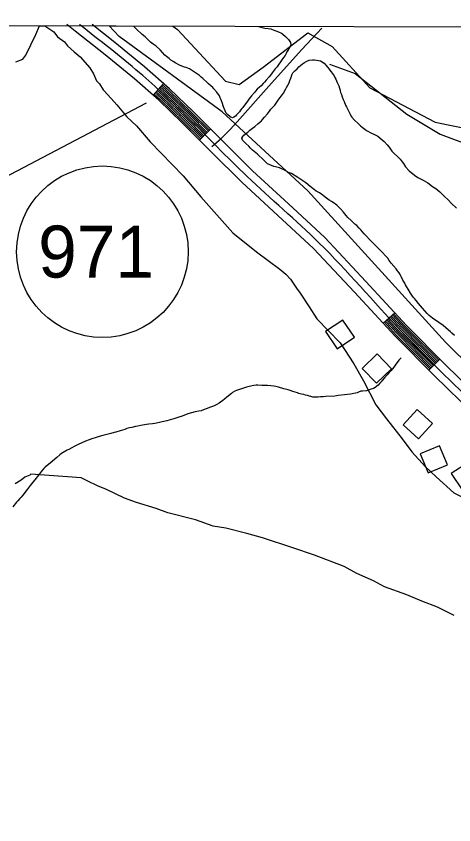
# Model space of a CAD drawing. Extents: x 3161564 to 3199464, y 849354 to 874788.
# Drawn here: x 3172453 to 3173295, y 871452 to 873008 of the extents above; entities that cross this region are included whole.
import ezdxf

# ---------------------------------------------------------------- set-up
doc = ezdxf.new("R2010")
doc.units = 0
for name, color, linetype in [('V-BLDG-OTLN', 7, 'Continuous'), ('V-GRID-FRAM', 7, 'Continuous'), ('V-ROAD-CNTR', 7, 'Continuous'), ('V-ROAD-IDEN', 7, 'Continuous'), ('V-SITE-VEGE', 7, 'Continuous'), ('V-TOPO-SHOR', 7, 'Continuous')]:
    doc.layers.add(name, color=color, linetype=linetype)

msp = doc.modelspace()

# ---------------------------------------------------------------- linework, layer by layer
at = {"layer": 'V-BLDG-OTLN'}
for points in [[(3173070.5478220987, 872367.4022375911), (3173103.7117557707, 872389.7641928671), (3173081.349800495, 872422.929126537), (3173048.1848668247, 872400.5671712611)], [(3173118.606725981, 872329.9433125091), (3173146.3426705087, 872301.1213701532), (3173175.1646128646, 872328.8563146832), (3173147.429668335, 872357.6792570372)], [(3173197.803567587, 872221.1485300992), (3173227.3615084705, 872194.1985839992), (3173254.311454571, 872223.7575248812), (3173224.7525136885, 872250.7074709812)], [(3173230.557502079, 872165.5876412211), (3173245.9314713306, 872128.6597150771), (3173282.858397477, 872144.0326843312), (3173267.485428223, 872180.960610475)], [(3173312.1623388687, 872094.2477839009), (3173345.6122719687, 872116.179740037), (3173323.6803158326, 872149.630673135), (3173290.2293827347, 872127.698716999)]]:
    msp.add_lwpolyline(points, close=True, dxfattribs=at)
at = {"layer": 'V-GRID-FRAM'}
msp.add_lwpolyline([(3165819.245, 873007.562), (3197186.656, 872920.878), (3197144.3310000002, 854733.305), (3165761.0470000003, 854820.033), (3165819.245, 873007.562)], dxfattribs=at)
at = {"layer": 'V-ROAD-CNTR'}
for p, q in [((3172716.635529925, 872855.3902616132), (3172736.5654900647, 872877.8142167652)), ((3172805.893351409, 872769.1114341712), (3172827.048309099, 872790.382391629)), ((3173159.3266445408, 872416.7121389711), (3173181.356600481, 872437.0750982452)), ((3173246.814469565, 872326.729318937), (3173268.128426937, 872347.8412767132))]:
    msp.add_line(p, q, dxfattribs=at)
for points in [[(3173333.7932956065, 872241.4854894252), (3173257.529448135, 872315.9123405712), (3173182.236598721, 872391.9271885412), (3173103.857755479, 872476.7210189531), (3173025.443912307, 872560.385851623), (3172956.7340497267, 872624.287723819), (3172887.0671890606, 872688.3535956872), (3172829.598303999, 872745.535481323), (3172772.3904184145, 872802.4323675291), (3172727.3935084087, 872845.8282807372), (3172680.860601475, 872887.1861980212), (3172624.0087151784, 872933.2991057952), (3172566.4518302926, 872979.0080143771), (3172550.6258619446, 872991.502989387)], [(3174323.151316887, 871475.958020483), (3174224.1495148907, 871536.5578992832), (3174124.9837132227, 871597.9347765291), (3174014.442934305, 871660.5176513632), (3173904.622153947, 871722.9685264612), (3173864.9882332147, 871749.3314737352), (3173826.8323095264, 871778.295415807), (3173779.5474040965, 871817.6653370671), (3173734.953493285, 871859.8592526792), (3173684.7135937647, 871914.028144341), (3173637.246688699, 871972.009028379), (3173355.035253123, 872262.6734470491), (3173278.665405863, 872337.204297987), (3173203.9145553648, 872412.671147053), (3173125.8177115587, 872497.1609780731), (3173046.627869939, 872581.6518090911), (3172977.1040089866, 872646.3136797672), (3172907.809147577, 872710.0355523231), (3172850.754261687, 872766.8054387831), (3172793.3823764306, 872823.8663246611), (3172747.7794676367, 872867.846236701), (3172700.284562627, 872910.0601522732), (3172642.7866776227, 872956.6950590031), (3172599.126764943, 872991.368989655)], [(3172829.265000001, 872756.6959999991), (3172847.240000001, 872772.199999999), (3172864.634000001, 872789.324999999), (3172878.362000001, 872804.2799999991), (3172939.457000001, 872873.1009999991), (3173001.780000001, 872943.1159999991), (3173021.648000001, 872964.0439999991), (3173041.309000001, 872984.773999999)], [(3172814.354334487, 872777.6204171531), (3172780.7874016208, 872811.0063503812), (3172735.547492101, 872854.6352631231), (3172724.6065139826, 872864.3602436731)], [(3172816.4703302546, 872779.747412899), (3172782.8863974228, 872813.1493460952), (3172737.586488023, 872856.837258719), (3172726.599509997, 872866.6022391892)], [(3172818.5863260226, 872781.8744086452), (3172784.9853932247, 872815.292341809), (3172739.625483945, 872859.0392543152), (3172728.592506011, 872868.844234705)], [(3172820.701321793, 872784.001404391), (3172787.0843890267, 872817.4363375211), (3172741.663479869, 872861.2412499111), (3172730.5855020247, 872871.0872302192)], [(3172822.817317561, 872786.1284001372), (3172789.1843848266, 872819.579333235), (3172743.702475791, 872863.4422455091), (3172732.578498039, 872873.3292257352)], [(3172824.932313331, 872788.2553958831), (3172791.2833806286, 872821.722328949), (3172745.740471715, 872865.6442411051), (3172734.571494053, 872875.571221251)], [(3172808.0083471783, 872771.2394299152), (3172774.489414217, 872804.5763632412), (3172729.4325043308, 872848.0302763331), (3172718.627525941, 872857.633257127)], [(3172810.123342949, 872773.3664256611), (3172776.588410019, 872806.7193589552), (3172731.4705002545, 872850.232271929), (3172720.6205219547, 872859.8752526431)], [(3172812.2393387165, 872775.493421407), (3172778.6884058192, 872808.8623546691), (3172733.5094961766, 872852.4332675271), (3172722.613517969, 872862.1172481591)], [(3173257.471448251, 872337.2862978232), (3173193.0755770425, 872402.2991677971), (3173170.341622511, 872426.894118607)], [(3173259.602443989, 872339.3972936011), (3173195.243572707, 872404.3731636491), (3173172.544618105, 872428.9301145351)], [(3173261.734439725, 872341.5082893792), (3173197.411568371, 872406.4481594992), (3173174.747613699, 872430.967110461)], [(3173263.865435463, 872343.620285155), (3173199.5795640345, 872408.5221553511), (3173176.950609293, 872433.0031063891)], [(3173265.9974311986, 872345.7312809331), (3173201.746559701, 872410.597151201), (3173179.153604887, 872435.0391023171)], [(3173248.9454653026, 872328.841314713), (3173184.4045943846, 872394.0011843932), (3173161.529640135, 872418.749134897)], [(3173251.0774610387, 872330.9523104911), (3173186.5715900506, 872396.076180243), (3173163.732635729, 872420.785130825)], [(3173253.2084567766, 872333.0643062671), (3173188.739585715, 872398.1501760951), (3173165.935631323, 872422.8211267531)], [(3173255.3404525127, 872335.1753020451), (3173190.907581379, 872400.225171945), (3173168.138626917, 872424.858122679)]]:
    msp.add_lwpolyline(points, dxfattribs=at)
msp.add_spline([(3173344.4142743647, 872252.0794682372), (3173193.0755770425, 872402.2991677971), (3173036.035891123, 872571.0188303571), (3172897.438168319, 872699.1945740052), (3172782.8863974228, 872813.1493460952), (3172690.5725820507, 872898.6231751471), (3172575.763811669, 872990.7679908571), (3172574.9178133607, 872991.4359895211)], degree=3, dxfattribs=at)
at = {"layer": 'V-ROAD-IDEN'}
msp.add_circle((3172618.975347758, 872554.3852328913), 165.0000000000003, dxfattribs=at)
msp.add_circle((3172618.975347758, 872554.3852328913), 165.0000000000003, dxfattribs=at)
at = {"layer": 'V-SITE-VEGE'}
for p, q in [((3172490.943000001, 872972.3429999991), (3172498.1904244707, 872989.1047003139)), ((3172498.1904244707, 872989.1047003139), (3172508.5101719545, 872989.0761816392)), ((3172508.5101719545, 872989.0761816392), (3172525.247000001, 872977.591999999)), ((3172650.974, 872968.7589999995), (3172631.7205323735, 872988.7356891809)), ((3172631.7205323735, 872988.7356891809), (3172754.785737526, 872988.3955978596)), ((3172754.785737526, 872988.3955978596), (3172763.329, 872981.9849999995)), ((3172471.393000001, 872932.662999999), (3172490.943000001, 872972.3429999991)), ((3172525.247000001, 872977.591999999), (3172532.729000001, 872967.981999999)), ((3172763.329, 872981.9849999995), (3172855.856, 872882.7979999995)), ((3172928.558, 872909.2479999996), (3173014.4760000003, 872975.3719999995)), ((3173014.4760000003, 872975.3719999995), (3173060.738, 872948.9219999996)), ((3172532.729000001, 872967.981999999), (3172545.912000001, 872958.2949999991)), ((3172545.912000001, 872958.2949999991), (3172551.515000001, 872950.6129999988)), ((3172849.247, 872823.2849999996), (3172650.974, 872968.7589999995)), ((3172551.515000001, 872950.6129999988), (3172564.676000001, 872939.0259999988)), ((3173060.738, 872948.9219999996), (3173133.44, 872869.5719999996)), ((3172452.197000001, 872919.606999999), (3172465.587000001, 872925.133999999)), ((3172465.587000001, 872925.133999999), (3172471.393000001, 872932.662999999)), ((3172564.676000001, 872939.0259999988), (3172575.958000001, 872929.3649999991)), ((3172575.958000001, 872929.3649999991), (3172594.693000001, 872908.192999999)), ((3172882.294, 872876.1849999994), (3172928.5580000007, 872909.2479999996)), ((3172594.693000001, 872908.192999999), (3172602.150000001, 872896.680999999)), ((3172602.150000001, 872896.680999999), (3172607.675000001, 872883.295999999)), ((3172607.675000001, 872883.295999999), (3172613.303000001, 872877.511999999)), ((3172855.8560000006, 872882.7979999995), (3172882.294, 872876.1849999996)), ((3172613.3030000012, 872877.511999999), (3172620.760000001, 872866.001999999)), ((3172620.760000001, 872866.001999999), (3172622.636000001, 872864.074999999)), ((3172622.636000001, 872864.074999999), (3172641.371000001, 872842.9029999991)), ((3173133.44, 872869.5719999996), (3173259.0130000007, 872803.4479999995)), ((3172641.371000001, 872842.9029999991), (3172647.001000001, 872837.1209999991)), ((3172647.001000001, 872837.1209999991), (3172665.7120000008, 872814.0489999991)), ((3173014.4760000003, 872671.1989999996), (3172849.247, 872823.2849999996)), ((3172665.7120000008, 872814.0489999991), (3172684.5000000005, 872796.6789999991)), ((3173259.0130000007, 872803.4479999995), (3173358.1460000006, 872783.6109999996)), ((3172684.500000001, 872796.6789999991), (3172710.716000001, 872765.8979999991)), ((3172710.716000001, 872765.8979999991), (3172774.5100000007, 872700.3779999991)), ((3172774.510000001, 872700.3779999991), (3172808.205000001, 872659.9879999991)), ((3173278.84, 872380.2489999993), (3173014.4760000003, 872671.1989999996)), ((3172808.205000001, 872659.9879999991), (3172870.047000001, 872590.6919999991)), ((3172870.047000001, 872590.6919999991), (3172915.201000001, 872553.9509999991)), ((3172915.201000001, 872553.9509999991), (3172960.4090000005, 872521.0129999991)), ((3172960.409000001, 872521.0129999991), (3172971.691000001, 872511.351999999)), ((3172971.691000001, 872511.3519999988), (3172981.073000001, 872501.7179999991)), ((3172981.073000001, 872501.7179999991), (3172992.255000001, 872484.4519999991)), ((3172992.255000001, 872484.4519999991), (3172999.732000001, 872474.839999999)), ((3172999.7320000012, 872474.839999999), (3173016.495000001, 872447.988999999)), ((3173016.495000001, 872447.988999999), (3173031.400000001, 872424.966999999)), ((3173031.400000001, 872424.966999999), (3173076.432000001, 872378.716999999)), ((3173635.732, 872029.7939999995), (3173278.84, 872380.2489999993)), ((3173076.432000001, 872378.716999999), (3173102.5190000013, 872338.4289999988)), ((3173102.5190000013, 872338.4289999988), (3173121.103000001, 872305.8479999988)), ((3173121.103000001, 872305.8479999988), (3173145.2180000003, 872259.8779999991)), ((3173145.218000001, 872259.8779999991), (3173165.780000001, 872232.9759999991)), ((3173165.780000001, 872232.9759999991), (3173195.697000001, 872194.5369999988)), ((3173195.697000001, 872194.5369999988), (3173214.385000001, 872169.5609999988)), ((3173214.385000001, 872169.5609999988), (3173240.624000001, 872140.6799999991)), ((3173240.6240000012, 872140.6799999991), (3173261.292000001, 872121.3859999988)), ((3172470.058000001, 872120.537999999), (3172462.3760000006, 872114.934999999)), ((3172479.618000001, 872124.216999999), (3172470.058000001, 872120.5379999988)), ((3172481.541000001, 872126.0929999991), (3172479.6180000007, 872124.216999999)), ((3172578.450000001, 872119.0929999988), (3172481.541000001, 872126.0929999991)), ((3172589.784000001, 872113.234999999), (3172578.450000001, 872119.0929999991)), ((3173261.2920000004, 872121.3859999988), (3173295.1130000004, 872090.501999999)), ((3172462.376000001, 872114.9349999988), (3172450.864000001, 872107.4799999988)), ((3172610.577000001, 872103.4479999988), (3172589.7840000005, 872113.2349999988)), ((3172625.712000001, 872097.5389999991), (3172610.577000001, 872103.447999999)), ((3172661.616000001, 872079.942999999), (3172625.712000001, 872097.5389999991)), ((3173295.113000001, 872090.501999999), (3173310.223000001, 872082.692999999)), ((3172684.334000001, 872072.0319999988), (3172661.616000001, 872079.942999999)), ((3172722.214000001, 872060.111999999), (3172684.334000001, 872072.0319999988)), ((3172744.932000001, 872052.202999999), (3172722.214000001, 872060.1119999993)), ((3172798.000000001, 872038.177999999), (3172744.932000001, 872052.2029999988)), ((3172832.077000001, 872026.3139999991), (3172798.000000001, 872038.177999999)), ((3172856.747000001, 872022.1789999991), (3172832.077000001, 872026.3139999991)), ((3172896.554000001, 872012.1379999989), (3172856.747000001, 872022.1789999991)), ((3172926.879000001, 872004.1259999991), (3172896.554000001, 872012.1379999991)), ((3172985.576000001, 871984.3219999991), (3172926.879000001, 872004.1259999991)), ((3173027.235000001, 871970.452999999), (3172985.576000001, 871984.3219999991)), ((3173084.003000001, 871948.7729999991), (3173027.235000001, 871970.452999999)), ((3173108.546000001, 871935.1309999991), (3173084.003000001, 871948.7729999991)), ((3173140.6980000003, 871921.386999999), (3173108.546000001, 871935.1309999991)), ((3173161.463000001, 871909.6989999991), (3173140.6980000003, 871921.386999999)), ((3173204.997000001, 871893.900999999), (3173161.463000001, 871909.6989999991)), ((3173233.368000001, 871882.1099999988), (3173204.9970000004, 871893.9009999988)), ((3173263.6440000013, 871870.292999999), (3173233.368000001, 871882.1099999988)), ((3173295.766000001, 871854.648999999), (3173263.6440000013, 871870.292999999))]:
    msp.add_line(p, q, dxfattribs=at)
at = {"layer": 'V-TOPO-SHOR'}
for points in [[(3172980.538000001, 872949.363999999), (3172977.853000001, 872944.9589999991), (3172976.203000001, 872942.3559999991), (3172974.140000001, 872939.1549999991), (3172972.479000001, 872935.7449999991), (3172970.814000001, 872932.133999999), (3172967.726000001, 872927.7329999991), (3172962.799000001, 872921.5419999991), (3172957.441000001, 872913.5399999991), (3172954.969000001, 872909.939999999), (3172951.483000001, 872905.947999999), (3172947.781000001, 872900.9509999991), (3172945.726000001, 872898.356999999), (3172942.439000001, 872894.1599999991), (3172939.767000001, 872890.5639999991), (3172934.032000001, 872884.5839999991), (3172930.751000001, 872880.792999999), (3172928.495000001, 872878.197999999), (3172924.194000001, 872873.6149999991), (3172920.925000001, 872870.8309999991), (3172916.633000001, 872866.851999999), (3172913.352000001, 872863.060999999), (3172911.300000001, 872860.6669999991), (3172905.760000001, 872854.0809999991), (3172902.884000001, 872850.484999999), (3172899.186000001, 872845.689999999), (3172896.716000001, 872842.2899999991), (3172892.597000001, 872836.2919999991), (3172889.310000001, 872832.0959999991), (3172887.260000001, 872829.9019999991), (3172884.995000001, 872826.501999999), (3172882.531000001, 872823.5059999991), (3172880.479000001, 872821.111999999), (3172877.204000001, 872817.724999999), (3172874.7490000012, 872815.334999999), (3172872.097000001, 872813.351999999), (3172869.250000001, 872811.7749999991), (3172864.834000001, 872813.6529999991), (3172859.647000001, 872818.1649999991), (3172857.265000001, 872821.224999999), (3172855.104000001, 872825.6959999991), (3172851.971000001, 872832.8039999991), (3172849.266000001, 872841.7229999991), (3172847.127000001, 872847.809999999), (3172845.753000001, 872850.6549999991), (3172843.986000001, 872854.3119999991), (3172839.435000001, 872861.238999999), (3172833.471000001, 872867.9809999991), (3172831.280000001, 872870.2309999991), (3172827.694000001, 872873.712999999), (3172823.299000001, 872877.204999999), (3172820.508000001, 872879.6639999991), (3172812.338000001, 872887.6499999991), (3172809.147000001, 872890.518999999), (3172805.549000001, 872893.1909999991), (3172799.956000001, 872897.506999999), (3172796.351000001, 872899.7779999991), (3172786.349000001, 872906.371999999), (3172783.338000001, 872907.8259999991), (3172780.123000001, 872908.878999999), (3172776.902000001, 872909.5279999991), (3172768.867000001, 872912.464999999), (3172759.250000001, 872917.8429999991), (3172756.243000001, 872919.4999999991), (3172750.837000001, 872922.802999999), (3172747.244000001, 872925.881999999), (3172742.251000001, 872929.7829999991), (3172739.263000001, 872932.8529999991), (3172730.316000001, 872942.8679999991), (3172722.130000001, 872949.6399999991), (3172716.731000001, 872953.547999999), (3172711.540000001, 872957.655999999), (3172706.751000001, 872961.9609999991), (3172701.181000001, 872967.8919999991), (3172695.793000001, 872972.608999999), (3172684.819000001, 872982.246999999), (3172679.010831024, 872988.6050021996)], [(3172919.131326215, 872987.9414279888), (3172919.885000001, 872987.5349999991), (3172923.706000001, 872986.4739999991), (3172931.356000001, 872984.7549999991), (3172938.001000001, 872983.655999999), (3172943.039000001, 872982.981999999), (3172948.866000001, 872980.8849999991), (3172952.884000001, 872979.415999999), (3172957.900000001, 872977.126999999), (3172963.319000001, 872974.832999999), (3172966.323000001, 872972.974999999), (3172971.1070000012, 872968.469999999), (3172974.495000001, 872965.192999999), (3172976.883000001, 872962.736999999), (3172981.040000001, 872956.623999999), (3172981.386000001, 872952.3809999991), (3172980.538000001, 872949.363999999)], [(3172891.137000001, 872778.6689999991), (3172898.485000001, 872784.626999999), (3172902.573000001, 872788.204999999), (3172908.072000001, 872791.763999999), (3172912.154000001, 872795.138999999), (3172918.283000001, 872800.506999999), (3172921.757000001, 872803.488999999), (3172924.825000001, 872806.474999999), (3172927.075000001, 872808.665999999), (3172931.175000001, 872813.253999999), (3172936.713000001, 872819.6399999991), (3172940.617000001, 872824.6329999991), (3172943.291000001, 872828.4319999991), (3172947.600000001, 872833.420999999), (3172950.470000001, 872836.6109999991), (3172957.054000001, 872845.810999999), (3172959.110000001, 872848.608999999), (3172960.961000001, 872851.006999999), (3172965.682000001, 872856.795999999), (3172967.333000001, 872859.3969999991), (3172971.886000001, 872867.613999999), (3172973.135000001, 872870.4239999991), (3172975.820000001, 872874.8269999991), (3172978.103000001, 872879.4389999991), (3172979.778000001, 872883.858999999), (3172981.251000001, 872888.2799999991), (3172982.719000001, 872892.2989999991), (3172983.774000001, 872895.716999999), (3172985.630000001, 872898.515999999), (3172989.320000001, 872902.7059999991), (3172993.611000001, 872906.4829999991), (3172997.092000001, 872910.0709999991), (3173000.361000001, 872912.851999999), (3173003.834000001, 872916.0369999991), (3173007.705000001, 872918.606999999), (3173012.381000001, 872920.9659999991), (3173016.845000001, 872922.7239999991), (3173023.524000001, 872923.8439999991), (3173027.157000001, 872923.7949999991), (3173031.185000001, 872923.1349999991), (3173038.632000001, 872921.4169999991), (3173045.437000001, 872917.087999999), (3173048.815000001, 872913.003999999), (3173052.591000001, 872908.7109999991), (3173054.574000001, 872906.060999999), (3173058.938000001, 872900.3489999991), (3173064.691000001, 872892.7999999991), (3173066.061000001, 872889.5519999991), (3173068.035000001, 872886.295999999), (3173070.777000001, 872880.2009999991), (3173073.712000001, 872873.2969999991), (3173076.221000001, 872864.785999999), (3173077.376000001, 872860.5299999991), (3173078.939000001, 872856.6719999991), (3173080.094000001, 872852.618999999), (3173082.043000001, 872847.545999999), (3173084.005000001, 872843.2799999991), (3173086.942000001, 872836.5769999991), (3173088.712000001, 872833.121999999), (3173095.388000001, 872819.3039999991)], [(3173055.805234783, 872915.2516869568), (3173105.5434608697, 872897.4880347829), (3173205.0199130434, 872819.3279652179), (3173268.96906087, 872780.2479304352), (3174334.788191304, 872382.3421217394), (3175333.105443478, 872012.858156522)], [(3171898.5032956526, 872394.7766782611), (3171926.9251391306, 872419.6457913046), (3172392.3328260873, 872677.2187478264), (3172704.084921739, 872840.6443478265)], [(3173095.388000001, 872819.3039999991), (3173096.754000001, 872815.8529999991), (3173099.138000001, 872812.993999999), (3173104.111000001, 872807.4739999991), (3173111.0900000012, 872801.121999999), (3173115.475000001, 872796.822999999), (3173118.870000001, 872794.1519999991), (3173123.665000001, 872790.4539999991), (3173127.060000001, 872787.7829999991), (3173136.676000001, 872782.199999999), (3173140.893000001, 872780.528999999), (3173145.103000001, 872778.4519999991), (3173148.716000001, 872776.7889999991), (3173157.297000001, 872769.606999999), (3173160.891000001, 872766.530999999), (3173166.8570000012, 872759.986999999), (3173170.435000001, 872755.6989999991), (3173175.981000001, 872747.952999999), (3173178.369000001, 872745.2949999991), (3173188.941000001, 872735.8659999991), (3173191.921000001, 872732.3949999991), (3173195.892000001, 872727.4959999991), (3173198.265000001, 872723.827999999), (3173202.423000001, 872717.716999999), (3173208.9820000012, 872710.1579999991), (3173219.366000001, 872701.7379999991), (3173226.171000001, 872697.4069999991), (3173232.182000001, 872694.094999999), (3173236.397000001, 872692.2209999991), (3173244.800000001, 872686.6569999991), (3173253.993000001, 872679.8699999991), (3173260.197000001, 872675.746999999), (3173264.192000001, 872672.6649999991), (3173268.186000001, 872669.381999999), (3173276.550000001, 872660.988999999), (3173284.926000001, 872653.4079999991), (3173290.100000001, 872647.682999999), (3173300.059000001, 872637.856999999)], [(3173296.334000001, 872393.0249999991), (3173291.550000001, 872397.5299999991), (3173288.758000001, 872400.192999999), (3173285.166000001, 872403.268999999), (3173274.586000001, 872412.0939999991), (3173266.193000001, 872418.464999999), (3173253.789000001, 872426.709999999), (3173247.796000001, 872431.432999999), (3173243.813000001, 872435.3239999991), (3173234.865000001, 872445.5399999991), (3173227.322000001, 872454.9299999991), (3173222.548000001, 872460.241999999), (3173219.573000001, 872464.118999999), (3173217.193000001, 872467.1789999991), (3173212.044000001, 872474.719999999), (3173207.100000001, 872482.2559999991), (3173204.3400000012, 872487.138999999), (3173202.372000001, 872490.797999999), (3173200.596000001, 872493.851999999), (3173197.243000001, 872499.751999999), (3173193.905000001, 872506.6599999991), (3173191.939000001, 872510.5229999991), (3173190.163000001, 872513.5759999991), (3173186.788000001, 872517.8609999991), (3173184.009000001, 872521.3319999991), (3173174.871000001, 872532.155999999), (3173170.902000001, 872537.2549999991), (3173167.934000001, 872541.7359999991), (3173165.548000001, 872544.3949999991), (3173155.798000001, 872554.822999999), (3173148.433000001, 872562.5929999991), (3173137.681000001, 872573.6419999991), (3173122.747000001, 872588.9859999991), (3173116.186000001, 872596.341999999), (3173113.202000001, 872599.6129999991), (3173108.221000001, 872604.525999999), (3173104.831000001, 872607.599999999), (3173097.854000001, 872614.155999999), (3173091.481000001, 872620.4999999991), (3173087.892000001, 872623.981999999), (3173082.932000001, 872630.305999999), (3173077.966000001, 872636.2289999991), (3173069.997000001, 872644.209999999), (3173063.196000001, 872648.743999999), (3173059.997000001, 872651.006999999), (3173055.389000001, 872653.6939999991), (3173050.189000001, 872657.197999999), (3173044.198000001, 872662.123999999), (3173041.405000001, 872664.5859999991), (3173036.801000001, 872667.4729999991), (3173034.200000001, 872669.123999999), (3173030.389000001, 872670.991999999), (3173026.989000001, 872673.461999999), (3173018.398000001, 872680.037999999), (3173010.214000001, 872686.809999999), (3173002.612000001, 872691.9609999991), (3172995.007000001, 872696.908999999), (3172982.998000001, 872704.5419999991), (3172977.1780000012, 872707.0449999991), (3172974.165000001, 872708.295999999), (3172970.358000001, 872710.366999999), (3172959.530000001, 872715.7629999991), (3172952.2860000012, 872717.677999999), (3172948.862000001, 872718.1279999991), (3172944.244000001, 872720.0079999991), (3172936.822000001, 872723.540999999), (3172932.834000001, 872727.229999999), (3172930.641000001, 872729.2779999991), (3172926.858000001, 872733.1649999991), (3172920.079000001, 872739.515999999), (3172917.288000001, 872741.974999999), (3172914.294000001, 872744.4389999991), (3172910.900000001, 872747.309999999), (3172907.906000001, 872749.976999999), (3172904.123000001, 872753.863999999), (3172900.535000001, 872757.1429999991), (3172894.758000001, 872762.8729999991), (3172891.174000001, 872766.5549999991), (3172888.788000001, 872769.2139999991), (3172887.424000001, 872772.8649999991), (3172888.884000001, 872776.2769999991), (3172891.137000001, 872778.6689999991)], [(3173193.649000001, 872350.0739999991), (3173189.551000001, 872345.6869999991), (3173186.262000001, 872341.2899999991), (3173183.591000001, 872337.8949999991), (3173179.684000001, 872332.4979999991), (3173173.730000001, 872325.3119999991), (3173171.477000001, 872322.9199999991), (3173169.429000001, 872320.7259999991), (3173166.556000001, 872317.332999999), (3173162.042000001, 872311.9419999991), (3173157.526000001, 872306.5519999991), (3173155.470000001, 872303.7549999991), (3173153.015000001, 872301.366999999), (3173149.736000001, 872297.775999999), (3173143.612000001, 872292.8119999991), (3173140.561000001, 872291.035999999), (3173136.106000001, 872290.087999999), (3173132.248000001, 872288.525999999), (3173126.972000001, 872286.577999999), (3173119.702000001, 872286.2729999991), (3173116.061000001, 872285.7159999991), (3173111.997000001, 872283.9539999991), (3173109.159000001, 872282.983999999), (3173096.205000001, 872280.533999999), (3173090.540000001, 872279.601999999), (3173084.470000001, 872278.6749999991), (3173072.344000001, 872277.6279999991), (3173066.073000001, 872276.704999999), (3173048.896000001, 872275.5249999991), (3173043.643000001, 872275.1909999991), (3173038.794000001, 872274.8529999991), (3173034.347000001, 872274.508999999), (3173028.091000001, 872274.594999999), (3173024.052000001, 872274.6499999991), (3173013.595000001, 872277.6179999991), (3173009.970000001, 872278.2729999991), (3173006.552000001, 872279.327999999), (3173002.1240000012, 872280.3969999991), (3172997.092000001, 872281.4759999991), (3172994.080000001, 872282.5269999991), (3172985.640000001, 872285.4679999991), (3172980.213000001, 872287.1549999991), (3172976.393000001, 872288.4189999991), (3172968.146000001, 872290.5489999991), (3172957.889000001, 872293.5169999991), (3172952.458000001, 872295.0009999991), (3172949.0360000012, 872295.6549999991), (3172943.191000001, 872296.3409999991), (3172936.535000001, 872296.8339999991), (3172925.437000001, 872297.1869999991), (3172917.765000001, 872297.2889999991), (3172914.535000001, 872297.3339999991), (3172910.491000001, 872296.782999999), (3172901.379000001, 872294.888999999), (3172896.517000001, 872293.540999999), (3172892.665000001, 872292.381999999), (3172882.7320000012, 872289.2849999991), (3172877.0530000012, 872287.3459999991), (3172874.007000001, 872286.1749999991), (3172869.531000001, 872283.609999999), (3172867.085000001, 872281.8269999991), (3172858.506000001, 872274.4739999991), (3172854.011000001, 872270.496999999), (3172850.949000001, 872268.1149999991), (3172846.261000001, 872264.7479999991), (3172843.406000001, 872262.7679999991), (3172839.132000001, 872260.2019999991), (3172832.427000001, 872256.858999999), (3172825.1240000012, 872254.3339999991), (3172820.254000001, 872252.582999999), (3172816.805000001, 872251.216999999), (3172809.092000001, 872248.2949999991), (3172804.638000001, 872247.3439999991), (3172797.3570000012, 872246.432999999), (3172783.375000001, 872242.586999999), (3172772.212000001, 872238.0959999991), (3172766.125000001, 872235.954999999), (3172756.192000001, 872232.8609999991), (3172743.220000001, 872229.2009999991), (3172734.105000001, 872226.900999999), (3172729.044000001, 872225.760999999), (3172719.728000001, 872223.6649999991), (3172715.683000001, 872223.1149999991), (3172708.206000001, 872222.6109999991), (3172703.956000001, 872221.8609999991), (3172696.268000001, 872220.5519999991), (3172693.032000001, 872220.1919999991), (3172687.158000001, 872218.858999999), (3172682.909000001, 872218.108999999), (3172675.616000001, 872216.187999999), (3172671.362000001, 872215.2379999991), (3172666.097000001, 872213.893999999), (3172661.839000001, 872212.540999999), (3172652.918000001, 872209.834999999), (3172645.010000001, 872207.3159999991), (3172641.766000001, 872206.351999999), (3172635.080000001, 872204.4239999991), (3172619.687000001, 872200.7969999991), (3172612.797000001, 872198.871999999), (3172606.913000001, 872196.729999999), (3172598.603000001, 872194.2189999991)], [(3172598.603000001, 872194.2189999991), (3172593.331000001, 872192.6749999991), (3172586.231000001, 872190.1479999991), (3172572.208000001, 872183.2729999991), (3172564.686000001, 872179.3359999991), (3172560.213000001, 872176.9729999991), (3172554.315000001, 872173.822999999), (3172551.065000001, 872172.454999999), (3172543.741000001, 872168.3139999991), (3172540.4820000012, 872166.136999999), (3172536.812000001, 872163.564999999), (3172531.092000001, 872158.5939999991), (3172527.617000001, 872155.4119999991), (3172522.507000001, 872150.836999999), (3172515.1610000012, 872145.0819999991), (3172512.714000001, 872143.096999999), (3172508.831000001, 872139.7179999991), (3172506.578000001, 872137.3259999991), (3172502.066000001, 872132.1379999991), (3172495.904000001, 872124.3479999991), (3172488.920000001, 872115.559999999), (3172485.023000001, 872110.9679999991), (3172480.091000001, 872104.5759999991), (3172474.537000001, 872096.979999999), (3172466.113000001, 872086.1909999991), (3172462.425000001, 872082.2059999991), (3172459.961000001, 872079.209999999), (3172456.275000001, 872075.221999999), (3172453.813000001, 872072.4289999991), (3172446.426000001, 872063.6469999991)]]:
    msp.add_lwpolyline(points, dxfattribs=at)

# ---------------------------------------------------------------- texts
at = {"layer": 'V-ROAD-IDEN'}
msp.add_text('971', height=100.00000200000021, rotation=359.8416625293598, dxfattribs=at).set_placement((3172495.2156514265, 872504.7270540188))

doc.saveas('drawing.dxf')
